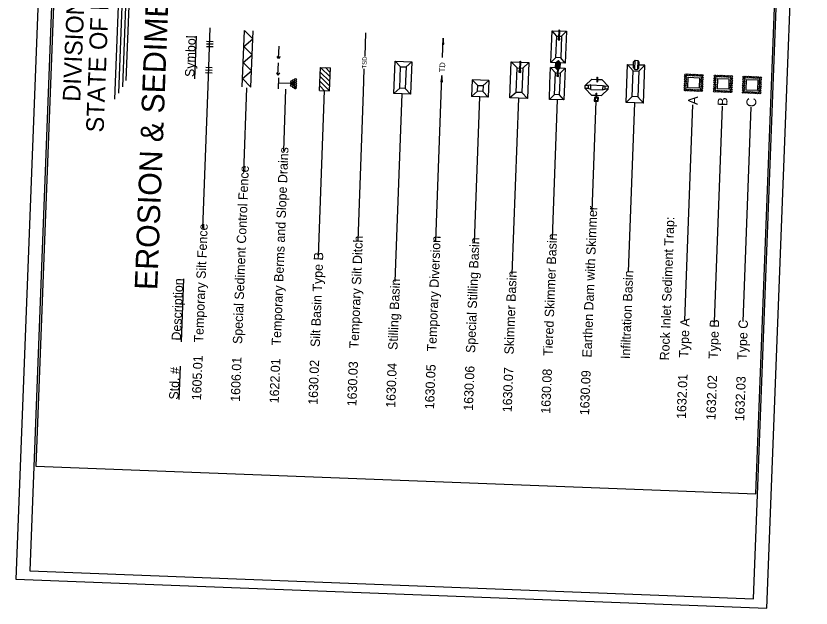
# Model space of a CAD drawing. Extents: x 2094746 to 2100565, y 682095 to 690719.
# Drawn here: x 2094746 to 2100565, y 682095 to 686425 of the extents above; entities that cross this region are included whole.
import ezdxf

# ---------------------------------------------------------------- set-up
doc = ezdxf.new("R2010")
doc.units = 0
for name, color, linetype in [('Default', 7, 'Continuous'), ('Exist Road Primary NC Shield CELL', 7, 'Continuous'), ('Sheet Cutting Line CELL', 7, 'Continuous'), ('Sheet Data Field CELL', 7, 'Continuous'), ('Sheet Plot Border Inside CELL', 7, 'Continuous'), ('Sheet Plot Border Outside CELL', 7, 'Continuous'), ('Sheet Title Data Points CELL', 7, 'Continuous')]:
    doc.layers.add(name, color=color, linetype=linetype)

msp = doc.modelspace()

# ---------------------------------------------------------------- linework, layer by layer
at = {"layer": 'Default'}
for p, q in [((2095471, 685815.7), (2095551.8, 687920.7)), ((2095498.7, 685860.8), (2095575.8, 687871.5)), ((2095527.7, 685905.8), (2095601.3, 687822.3)), ((2095554.1, 685953), (2095623.9, 687773.2))]:
    msp.add_line(p, q, dxfattribs=at)
at = {"layer": 'Exist Road Primary NC Shield CELL'}
for p, q in [((2098912, 685916.5), (2098961.9, 685962.6)), ((2098961.9, 685962.6), (2098997.5, 685961.3)), ((2098998.1, 685976.7), (2098996.8, 685944.5)), ((2098998.1, 685976.7), (2099002.7, 685976.6)), ((2099002.7, 685976.6), (2099001.4, 685944.3)), ((2099002.1, 685961.1), (2099034.8, 685959.9)), ((2099034.8, 685959.9), (2099081.9, 685909.9)), ((2098911.2, 685895.1), (2098912, 685916.5)), ((2098936.5, 685894.1), (2098911.2, 685895.1)), ((2098911.2, 685895.1), (2098957.4, 685846.2)), ((2098937.3, 685915.5), (2098912, 685916.5)), ((2098936.5, 685894.1), (2098937.3, 685915.5)), ((2098953.2, 685888.4), (2098936.5, 685894.1)), ((2098954.5, 685920.8), (2098937.3, 685915.5)), ((2098953.2, 685888.4), (2098954.5, 685920.8)), ((2098954.5, 685920.8), (2099039.9, 685917.6)), ((2098996.8, 685944.5), (2099001.4, 685944.3)), ((2099040, 685917.7), (2099038.7, 685885.2)), ((2099040, 685917.7), (2099056.6, 685910.9)), ((2099056.6, 685910.9), (2099055.8, 685889.5)), ((2099081.9, 685909.9), (2099056.6, 685910.9)), ((2099081.1, 685888.5), (2099081.9, 685909.9)), ((2098953.2, 685888.4), (2099038.7, 685885.2)), ((2098957.4, 685846.2), (2098992.8, 685844.8)), ((2098992.1, 685828.7), (2098993.5, 685861.6)), ((2098993.5, 685861.6), (2098998.2, 685861.5)), ((2098996.9, 685828.5), (2098998.2, 685861.5)), ((2098997.5, 685844.7), (2099032.3, 685843.4)), ((2099032.3, 685843.4), (2099081.1, 685888.5)), ((2099038.7, 685885.2), (2099055.8, 685889.5)), ((2099081.1, 685888.5), (2099055.8, 685889.5)), ((2098980, 685829.1), (2098978.9, 685802.3)), ((2098978.9, 685802.3), (2099008, 685801.2)), ((2099009, 685828), (2098980, 685829.1)), ((2098984.6, 685824.2), (2098983.9, 685806.9)), ((2098983.9, 685806.9), (2099003.4, 685806.1)), ((2099004.1, 685823.5), (2098984.6, 685824.2)), ((2099003.4, 685806.1), (2099004.1, 685823.5)), ((2099008, 685801.2), (2099009, 685828))]:
    msp.add_line(p, q, dxfattribs=at)
at = {"layer": 'Sheet Data Field CELL'}
for p, q in [((2096152.2, 685911.5), (2096168.6, 686339.2)), ((2096402.5, 685906.9), (2096418.4, 686319.1)), ((2096479.7, 686257.9), (2096418.4, 686319.1)), ((2096466.2, 685905.5), (2096481.9, 686316.6)), ((2097300.9, 686130.1), (2097307.4, 686300.7)), ((2098664.7, 686200.7), (2098669.2, 686316.8)), ((2098669.2, 686316.8), (2098775.6, 686312.8)), ((2098704.3, 686278.5), (2098669.2, 686316.8)), ((2098720.1, 686261.1), (2098722.6, 686322.5)), ((2098724.5, 686322.4), (2098722.1, 686261)), ((2098722.6, 686322.5), (2098724.5, 686322.4)), ((2098739, 686277.1), (2098775.6, 686312.8)), ((2098775.7, 686313), (2098771.2, 686196.7)), ((2096054.9, 685965.6), (2096066.7, 686276.7)), ((2096413.9, 686201.6), (2096479.7, 686257.9)), ((2097873.3, 686263.3), (2097867.3, 686219.1)), ((2097867.9, 686120.8), (2097873.3, 686263.3)), ((2097877.3, 686220), (2097873.3, 686263.3)), ((2098698.3, 686120.2), (2098704.6, 686278.4)), ((2098704.6, 686278.4), (2098739, 686277.1)), ((2098715.1, 686261.3), (2098714.7, 686250.2)), ((2098714.7, 686250.2), (2098726.7, 686249.7)), ((2098727.1, 686260.8), (2098715.1, 686261.3)), ((2098717, 686259.3), (2098716.7, 686252.1)), ((2098716.7, 686252.1), (2098724.8, 686251.8)), ((2098725.1, 686259), (2098717, 686259.3)), ((2098724.8, 686251.8), (2098725.1, 686259)), ((2098726.7, 686249.7), (2098727.1, 686260.8)), ((2098739, 686277.1), (2098732.8, 686118.9)), ((2096140.7, 686202.7), (2096188.8, 686201)), ((2096141.4, 686222.4), (2096189.4, 686220.5)), ((2096142.1, 686240.6), (2096190.3, 686238.8)), ((2096475.1, 686140.4), (2096413.9, 686201.6)), ((2097867.3, 686219.1), (2097877.3, 686220)), ((2098660.2, 686084.5), (2098664.7, 686200.7)), ((2098771.2, 686196.7), (2098766.7, 686080.4)), ((2096409.4, 686084.1), (2096475.1, 686140.4)), ((2096668.6, 686114.4), (2096659.2, 686129.2)), ((2096679, 686128.4), (2096668.6, 686114.4)), ((2096470.8, 686022.9), (2096409.4, 686084.1)), ((2097512.9, 685858.6), (2097521.9, 686094.5)), ((2097561.5, 686053.6), (2097521.9, 686094.5)), ((2097521.9, 686094.5), (2097642.4, 686089.9)), ((2097601.2, 686052.2), (2097642.4, 686089.9)), ((2097642.4, 686089.9), (2097633.3, 685854)), ((2098365.9, 685957.3), (2098371, 686088.4)), ((2098371, 686088.4), (2098500.6, 686083.5)), ((2098413.9, 686045), (2098371, 686088.4)), ((2098433.2, 686025.3), (2098436, 686094.7)), ((2098438.4, 686094.6), (2098435.6, 686025.2)), ((2098436, 686094.7), (2098438.4, 686094.6)), ((2098456.1, 686043.3), (2098500.6, 686083.5)), ((2098500.7, 686083.7), (2098495.5, 685952.4)), ((2098698.3, 686120.2), (2098660.2, 686084.5)), ((2098696.9, 686083.1), (2098660.2, 686084.5)), ((2098695.6, 686045.9), (2098696.9, 686083.1)), ((2098696.9, 686083.1), (2098706.7, 686092.1)), ((2098732.8, 686118.9), (2098698.3, 686120.2)), ((2098704.7, 686036.1), (2098706.7, 686092.1)), ((2098706.7, 686092.1), (2098722.3, 686091.5)), ((2098710.3, 685994.9), (2098714.5, 686100.5)), ((2098716.4, 686100.4), (2098712.3, 685994.8)), ((2098714.5, 686100.5), (2098716.4, 686100.4)), ((2098722.3, 686091.5), (2098720.2, 686035.6)), ((2098731.4, 686081.8), (2098722.3, 686091.5)), ((2098730, 686044.6), (2098731.4, 686081.8)), ((2098766.7, 686080.4), (2098731.4, 686081.8)), ((2098766.7, 686080.4), (2098732.9, 686119)), ((2099216.1, 685930.9), (2099221.5, 686069.3)), ((2099263.3, 686023.6), (2099221.5, 686069.3)), ((2099221.5, 686069.3), (2099265.4, 686067.7)), ((2099264.6, 686045.5), (2099266.2, 686089.8)), ((2099266.2, 686089.8), (2099277.8, 686100.6)), ((2099275.4, 686033.8), (2099277.8, 686100.6)), ((2099277.8, 686100.6), (2099296.4, 686099.9)), ((2099296.4, 686099.9), (2099293.9, 686033.2)), ((2099307.2, 686088.2), (2099296.4, 686099.9)), ((2099305.6, 686044), (2099307.2, 686088.2)), ((2096133.3, 686011.8), (2096181.6, 686009.9)), ((2096134, 686031.4), (2096182.2, 686029.5)), ((2096134.8, 686049.7), (2096182.9, 686047.8)), ((2096404.9, 685966.8), (2096470.8, 686022.9)), ((2096967.9, 685880.1), (2096974.4, 686048.9)), ((2096973.1, 686014.9), (2097044.3, 685945.5)), ((2096974.4, 686048.9), (2097045.6, 685979.5)), ((2096974.4, 686048.9), (2097048.1, 686046.2)), ((2097011.3, 686047.5), (2097046.8, 686012.2)), ((2097041.6, 685877.4), (2097048.1, 686046.2)), ((2097288.9, 685867.9), (2097295.4, 686038.5)), ((2098407.1, 685866.2), (2098414.2, 686044.9)), ((2098414.2, 686044.9), (2098456.1, 686043.3)), ((2098427.1, 686025.5), (2098426.6, 686013)), ((2098426.6, 686013), (2098441.3, 686012.4)), ((2098441.7, 686025), (2098427.1, 686025.5)), ((2098429.4, 686023.2), (2098429.1, 686015.1)), ((2098429.1, 686015.1), (2098438.9, 686014.7)), ((2098439.3, 686022.9), (2098429.4, 686023.2)), ((2098438.9, 686014.7), (2098439.3, 686022.9)), ((2098441.3, 686012.4), (2098441.7, 686025)), ((2098456.1, 686043.3), (2098449.1, 685864.7)), ((2098654.3, 685931.1), (2098658.9, 686047.3)), ((2098694, 686009), (2098658.9, 686047.3)), ((2098695.6, 686045.9), (2098658.9, 686047.3)), ((2098695.6, 686045.9), (2098704.7, 686036.1)), ((2098704.7, 686036.1), (2098720.2, 686035.6)), ((2098730, 686044.6), (2098720.2, 686035.6)), ((2098728.6, 686007.6), (2098765.3, 686043.3)), ((2098730, 686044.6), (2098765.3, 686043.3)), ((2098765.3, 686043.4), (2098760.8, 685927.2)), ((2099256.1, 685835), (2099263.7, 686023.5)), ((2099263.7, 686023.5), (2099304.6, 686022)), ((2099264.6, 686045.5), (2099275.4, 686033.8)), ((2099275.4, 686033.8), (2099293.9, 686033.2)), ((2099305.6, 686044), (2099293.9, 686033.2)), ((2099304.6, 686022), (2099297.2, 685833.5)), ((2099304.6, 686022), (2099348.3, 686064.5)), ((2099348.3, 686064.5), (2099306.3, 686066.1)), ((2099337.6, 685787.5), (2099348.3, 686064.5)), ((2096466.2, 685905.5), (2096404.9, 685966.8)), ((2096663.9, 685992.8), (2096654.7, 686008.8)), ((2096663.9, 685992.8), (2096654.7, 686008.8)), ((2096674.5, 686008.1), (2096663.9, 685992.8)), ((2096674.5, 686008.1), (2096663.9, 685992.8)), ((2096667.1, 685893.1), (2096670.3, 685972.9)), ((2096971.9, 685982.2), (2097042.9, 685911.4)), ((2097638, 685975.7), (2097633.3, 685854)), ((2097862.7, 685988.7), (2097856.9, 685944.4)), ((2097857.3, 685846), (2097862.7, 685988.7)), ((2097866.7, 685944), (2097862.7, 685988.7)), ((2098086, 685958.5), (2098081.3, 685836.8)), ((2098206.4, 685953.9), (2098086, 685958.5)), ((2098125.6, 685917.7), (2098086, 685958.5)), ((2098165.2, 685916.2), (2098206.4, 685953.9)), ((2098206.4, 685953.9), (2098201.7, 685832.2)), ((2098360.9, 685826.1), (2098365.9, 685957.3)), ((2098495.5, 685952.4), (2098490.5, 685821)), ((2098687.9, 685850.7), (2098694.3, 686008.9)), ((2098694.3, 686008.9), (2098728.6, 686007.6)), ((2098705.3, 685995.1), (2098704.9, 685984)), ((2098704.9, 685984), (2098716.9, 685983.5)), ((2098717.3, 685994.6), (2098705.3, 685995.1)), ((2098707.2, 685993), (2098706.9, 685985.8)), ((2098706.9, 685985.8), (2098715, 685985.5)), ((2098715.3, 685992.7), (2098707.2, 685993)), ((2098715, 685985.5), (2098715.3, 685992.7)), ((2098716.9, 685983.5), (2098717.3, 685994.6)), ((2098728.6, 686007.6), (2098722.4, 685849.4)), ((2096115, 684872.5), (2096152.2, 685911.5)), ((2096415.3, 685281.4), (2096436.4, 685900.6)), ((2096756.6, 685930.4), (2096670.1, 685933.6)), ((2096970.5, 685948.1), (2097041.6, 685877.4)), ((2096970.6, 685914.2), (2097004.8, 685878.7)), ((2097555.4, 685896.2), (2097512.9, 685858.6)), ((2097555.4, 685896.2), (2097512.9, 685858.6)), ((2097633.3, 685854), (2097595.1, 685894.7)), ((2097633.3, 685854), (2097595.1, 685894.7)), ((2097856.9, 685944.4), (2097866.7, 685944)), ((2098649.9, 685815), (2098654.3, 685931.1)), ((2098760.8, 685927.2), (2098756.3, 685810.8)), ((2099210.8, 685792.5), (2099216.1, 685930.9)), ((2096705.9, 685438.5), (2096720.6, 685889.7)), ((2096960.9, 684668.1), (2097004.7, 685878.8)), ((2096967.9, 685880.1), (2097041.6, 685877.4)), ((2097250, 684782.6), (2097288.9, 685867.9)), ((2097633.3, 685854), (2097512.9, 685858.6)), ((2097633.3, 685854), (2097512.9, 685858.6)), ((2097522.2, 684481.9), (2097573.1, 685856.3)), ((2097819.1, 684780.3), (2097857.3, 685846)), ((2098123.8, 685874.4), (2098081.3, 685836.8)), ((2098201.7, 685832.2), (2098081.3, 685836.8)), ((2098201.7, 685832.2), (2098163.5, 685872.9)), ((2098407.1, 685866.2), (2098360.9, 685826.1)), ((2098449.1, 685864.7), (2098407.1, 685866.2)), ((2098490.5, 685821), (2098449.2, 685864.8)), ((2098687.9, 685850.7), (2098649.9, 685815)), ((2098722.4, 685849.4), (2098687.9, 685850.7)), ((2098756.3, 685810.8), (2098722.6, 685849.5)), ((2099256.1, 685835), (2099210.8, 685792.5)), ((2099297.2, 685833.5), (2099256.1, 685835)), ((2098102.1, 684771.9), (2098141.5, 685834.5)), ((2098490.5, 685821), (2098360.9, 685826.1)), ((2098378, 684536.2), (2098425.7, 685823.6)), ((2098756.3, 685810.8), (2098649.9, 685815)), ((2098672.3, 684799.7), (2098709.9, 685812.6)), ((2098963.6, 684996.4), (2098993.5, 685801.8)), ((2099337.6, 685787.5), (2099210.8, 685792.5)), ((2099228.4, 684554.4), (2099274.2, 685790)), ((2099337.6, 685787.5), (2099297.4, 685833.6)), ((2099641.8, 684197.4), (2099700.3, 685774.6)), ((2099858, 684188.6), (2099916.4, 685766.3)), ((2100068.5, 684191), (2100126.5, 685758.3)), ((2095957.1, 684041.8), (2095974.8, 684502.2)), ((2095940.9, 683619), (2095950, 683864.1)), ((2100242.3, 682094.5), (2100242.3, 682094.5))]:
    msp.add_line(p, q, dxfattribs=at)
for points in [[(2096668.6, 686114.4), (2096671.9, 686203.4)], [(2096663.9, 685992.8), (2096667.3, 686081.7)], [(2096663.9, 685992.8), (2096667.3, 686081.7)]]:
    msp.add_lwpolyline(points, dxfattribs=at)
for points in [[(2097595.1, 685894.7), (2097555.4, 685896.2), (2097561.5, 686053.6), (2097601.2, 686052.2)], [(2099663, 685899.2), (2099665.9, 685976.5), (2099749.4, 685973.2), (2099746.6, 685897.3)], [(2099879.2, 685890.9), (2099882, 685968.2), (2099964.3, 685965.1), (2099962.7, 685889)], [(2100089.2, 685882.8), (2100092.1, 685960), (2100175.7, 685956.8), (2100172.9, 685880.9)], [(2098163.5, 685872.9), (2098123.8, 685874.4), (2098125.6, 685917.7), (2098165.2, 685916.2)]]:
    msp.add_lwpolyline(points, close=True, dxfattribs=at)
for centre, major_axis in [((2096764.6, 685945.1), (-7.36, 0.28)), ((2096777.8, 685953.6), (-7.36, 0.28)), ((2096791.1, 685945.9), (-7.36, 0.28)), ((2096791.7, 685960.8), (-7.36, 0.28)), ((2099645.6, 685947.1), (7.1, -0.27)), ((2099646.2, 685963), (7.1, -0.27)), ((2099646.9, 685978.9), (7.1, -0.27)), ((2099647.5, 685994.8), (7.1, -0.27)), ((2099664.7, 685994.1), (7.1, -0.27)), ((2099681.9, 685993.5), (7.1, -0.27)), ((2099699.1, 685992.8), (7.1, -0.27)), ((2099716.3, 685992.1), (7.1, -0.27)), ((2099733.5, 685991.5), (7.1, -0.27)), ((2099750.7, 685990.8), (7.1, -0.27)), ((2099766.7, 685958.4), (7.1, -0.27)), ((2099767.3, 685974.3), (7.1, -0.27)), ((2099767.9, 685990.2), (7.1, -0.27)), ((2099861.7, 685954.8), (7.1, -0.27)), ((2099862.3, 685970.7), (7.1, -0.27)), ((2099862.9, 685986.6), (7.1, -0.27)), ((2099880.1, 685985.9), (7.1, -0.27)), ((2099897.3, 685985.3), (7.1, -0.27)), ((2099914.5, 685984.6), (7.1, -0.27)), ((2099931.8, 685984), (7.1, -0.27)), ((2099949, 685983.3), (7.1, -0.27)), ((2099966.2, 685982.6), (7.1, -0.27)), ((2099982.2, 685950.2), (7.1, -0.27)), ((2099982.8, 685966.1), (7.1, -0.27)), ((2099983.4, 685982), (7.1, -0.27)), ((2100072.5, 685946.6), (7.1, -0.27)), ((2100073.1, 685962.5), (7.1, -0.27)), ((2100073.7, 685978.4), (7.1, -0.27)), ((2100090.9, 685977.8), (7.1, -0.27)), ((2100108.1, 685977.1), (7.1, -0.27)), ((2100125.3, 685976.4), (7.1, -0.27)), ((2100142.5, 685975.8), (7.1, -0.27)), ((2100159.8, 685975.1), (7.1, -0.27)), ((2100177, 685974.5), (7.1, -0.27)), ((2100193.6, 685957.9), (7.1, -0.27)), ((2100194.2, 685973.8), (7.1, -0.27)), ((2096764, 685930.2), (-7.36, 0.28)), ((2096764.1, 685915.9), (-7.36, 0.28)), ((2096777.3, 685907), (-7.36, 0.28)), ((2096777.9, 685922.5), (-7.36, 0.28)), ((2096778.5, 685936.8), (-7.36, 0.28)), ((2096790.6, 685898.1), (-7.36, 0.28)), ((2096791.2, 685913.6), (-7.36, 0.28)), ((2096791.7, 685928.5), (-7.36, 0.28)), ((2099643.8, 685899.4), (7.1, -0.27)), ((2099644.4, 685915.3), (7.1, -0.27)), ((2099645, 685931.2), (7.1, -0.27)), ((2099764.3, 685894.8), (7.1, -0.27)), ((2099764.9, 685910.7), (7.1, -0.27)), ((2099765.5, 685926.6), (7.1, -0.27)), ((2099766.1, 685942.5), (7.1, -0.27)), ((2099859.3, 685891.3), (7.1, -0.27)), ((2099859.9, 685907.1), (7.1, -0.27)), ((2099860.5, 685923), (7.1, -0.27)), ((2099861.1, 685938.9), (7.1, -0.27)), ((2099979.7, 685886.6), (7.1, -0.27)), ((2099980.3, 685902.5), (7.1, -0.27)), ((2099980.9, 685918.4), (7.1, -0.27)), ((2099981.6, 685934.3), (7.1, -0.27)), ((2100070.7, 685899), (7.1, -0.27)), ((2100071.3, 685914.9), (7.1, -0.27)), ((2100071.9, 685930.8), (7.1, -0.27)), ((2100191.1, 685894.3), (7.1, -0.27)), ((2100191.7, 685910.2), (7.1, -0.27)), ((2100192.3, 685926.1), (7.1, -0.27)), ((2100192.9, 685942), (7.1, -0.27)), ((2099643.2, 685883.5), (7.1, -0.27)), ((2099660.4, 685882.9), (7.1, -0.27)), ((2099677.6, 685882.2), (7.1, -0.27)), ((2099694.8, 685881.6), (7.1, -0.27)), ((2099712, 685880.9), (7.1, -0.27)), ((2099729.2, 685880.2), (7.1, -0.27)), ((2099746.4, 685879.6), (7.1, -0.27)), ((2099763.7, 685878.9), (7.1, -0.27)), ((2099858.7, 685875.4), (7.1, -0.27)), ((2099875.9, 685874.7), (7.1, -0.27)), ((2099893.1, 685874), (7.1, -0.27)), ((2099910.3, 685873.4), (7.1, -0.27)), ((2099927.5, 685872.7), (7.1, -0.27)), ((2099944.7, 685872.1), (7.1, -0.27)), ((2099961.9, 685871.4), (7.1, -0.27)), ((2099979.1, 685870.7), (7.1, -0.27)), ((2100069.4, 685867.2), (7.1, -0.27)), ((2100070, 685883.1), (7.1, -0.27)), ((2100086.6, 685866.5), (7.1, -0.27)), ((2100103.9, 685865.9), (7.1, -0.27)), ((2100121.1, 685865.2), (7.1, -0.27)), ((2100138.3, 685864.5), (7.1, -0.27)), ((2100155.5, 685863.9), (7.1, -0.27)), ((2100172.7, 685863.2), (7.1, -0.27)), ((2100189.9, 685862.6), (7.1, -0.27)), ((2100190.5, 685878.5), (7.1, -0.27))]:
    msp.add_ellipse(centre, major_axis=major_axis, ratio=0.923408, dxfattribs=at)
at = {"layer": 'Sheet Plot Border Inside CELL'}
msp.add_lwpolyline([(2100242.3, 682094.5), (2100565.2, 690508.1), (2095069.1, 690719.1), (2094746.1, 682305.5)], close=True, dxfattribs=at)
at = {"layer": 'Sheet Plot Border Outside CELL'}
msp.add_lwpolyline([(2100144.4, 682163.3), (2100464, 690489.5), (2095168.6, 690692.8), (2094849, 682366.6)], close=True, dxfattribs=at)
at = {"layer": 'Sheet Title Data Points CELL'}
for p, q in [((2094891, 683133.2), (2094891, 683133.2)), ((2100161.3, 682931), (2100161.3, 682931))]:
    msp.add_line(p, q, dxfattribs=at)
msp.add_lwpolyline([(2095178.7, 690629.8), (2094891, 683133.2), (2100161.3, 682931), (2100449, 690427.5)], close=True, dxfattribs=at)

# ---------------------------------------------------------------- texts
at = {"layer": 'Default'}
for s, height, p in [('EROSION & SEDIMENT CONTROL LEGEND', 165.585, (2095780.4, 684418.3)), ('STATE OF NORTH CAROLINA', 128.788, (2095387.9, 685571.4))]:
    msp.add_text(s, height=height, rotation=87.80199, dxfattribs=at).set_placement(p)
at = {"layer": 'Sheet Cutting Line CELL'}
msp.add_text(' DIVISION OF HIGHWAYS', height=128.788, rotation=87.57092, dxfattribs=at).set_placement((2095214.8, 685748.2))
at = {"layer": 'Sheet Data Field CELL'}
for s, height, p in [('Symbol', 68.14, (2096051.1, 685977.5)), ('TSD', 31.85, (2097311.1, 686040.4)), ('TD', 41.32, (2097885.6, 686012)), ('A', 71.8, (2099736.1, 685773.3)), ('B', 71.8, (2099952.3, 685765)), ('C', 71.8, (2100162.4, 685756.9)), ('Temporary Berms and Slope Drains ', 68.045, (2096685.2, 684013.9)), ('Special Sediment Control Fence', 68.14, (2096401.1, 684024.8)), ('Earthen Dam with Skimmer', 68.14, (2098958.5, 683926.2)), ('Temporary Silt Fence', 68.14, (2096116.9, 684035.7)), ('Rock Inlet Sediment Trap:', 68.045, (2099525.5, 683904.9)), ('Temporary Silt Ditch', 68.14, (2097253.7, 683992.1)), ('Temporary Diversion', 68.167, (2097822.1, 683970.2)), ('Special Stilling Basin', 68.14, (2098106.3, 683959.3)), ('Tiered Skimmer Basin', 68.14, (2098672.4, 683937.6)), ('Silt Basin Type B', 68.14, (2096969.5, 684003)), ('Skimmer Basin', 68.14, (2098388.2, 683948.5)), ('Infiltration Basin', 68.14, (2099239, 683914.9)), ('Description', 68.14, (2095953.1, 684049.9)), ('Stilling Basin', 68.14, (2097537.9, 683981.2)), (' Type A', 68.14, (2099665, 683899.5)), (' Type B', 68.14, (2099881.2, 683891.2)), (' Type C', 68.14, (2100091.3, 683883.1)), ('1605.01', 68.05, (2096100.6, 683612.9)), ('1606.01', 68.05, (2096384.8, 683602)), ('1622.01', 68.05, (2096669, 683591.1)), ('Std. #', 68.14, (2095934.8, 683618.1)), ('1630.02', 68.05, (2096953.2, 683580.2)), ('1630.03', 68.05, (2097237.4, 683569.2)), ('1630.04', 68.05, (2097521.6, 683558.3)), ('1630.05', 68.05, (2097805.8, 683547.4)), ('1630.06', 68.05, (2098090, 683536.5)), ('1630.07', 68.05, (2098374.2, 683525.6)), ('1630.08', 68.05, (2098656.1, 683514.8)), ('1630.09', 68.05, (2098940.3, 683503.9)), ('1632.01', 68.05, (2099648.7, 683476.7)), ('1632.02', 68.05, (2099864.9, 683468.4)), ('1632.03', 68.05, (2100075, 683460.3))]:
    msp.add_text(s, height=height, rotation=87.80201, dxfattribs=at).set_placement(p)

doc.saveas('drawing.dxf')
